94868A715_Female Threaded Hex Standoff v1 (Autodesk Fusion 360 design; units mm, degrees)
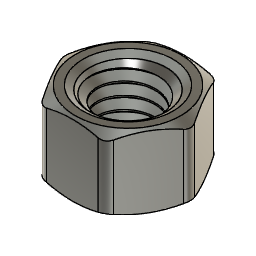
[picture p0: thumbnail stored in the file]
description: STEP AP203
part number: 94868A715_Female Threaded Hex Standoff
